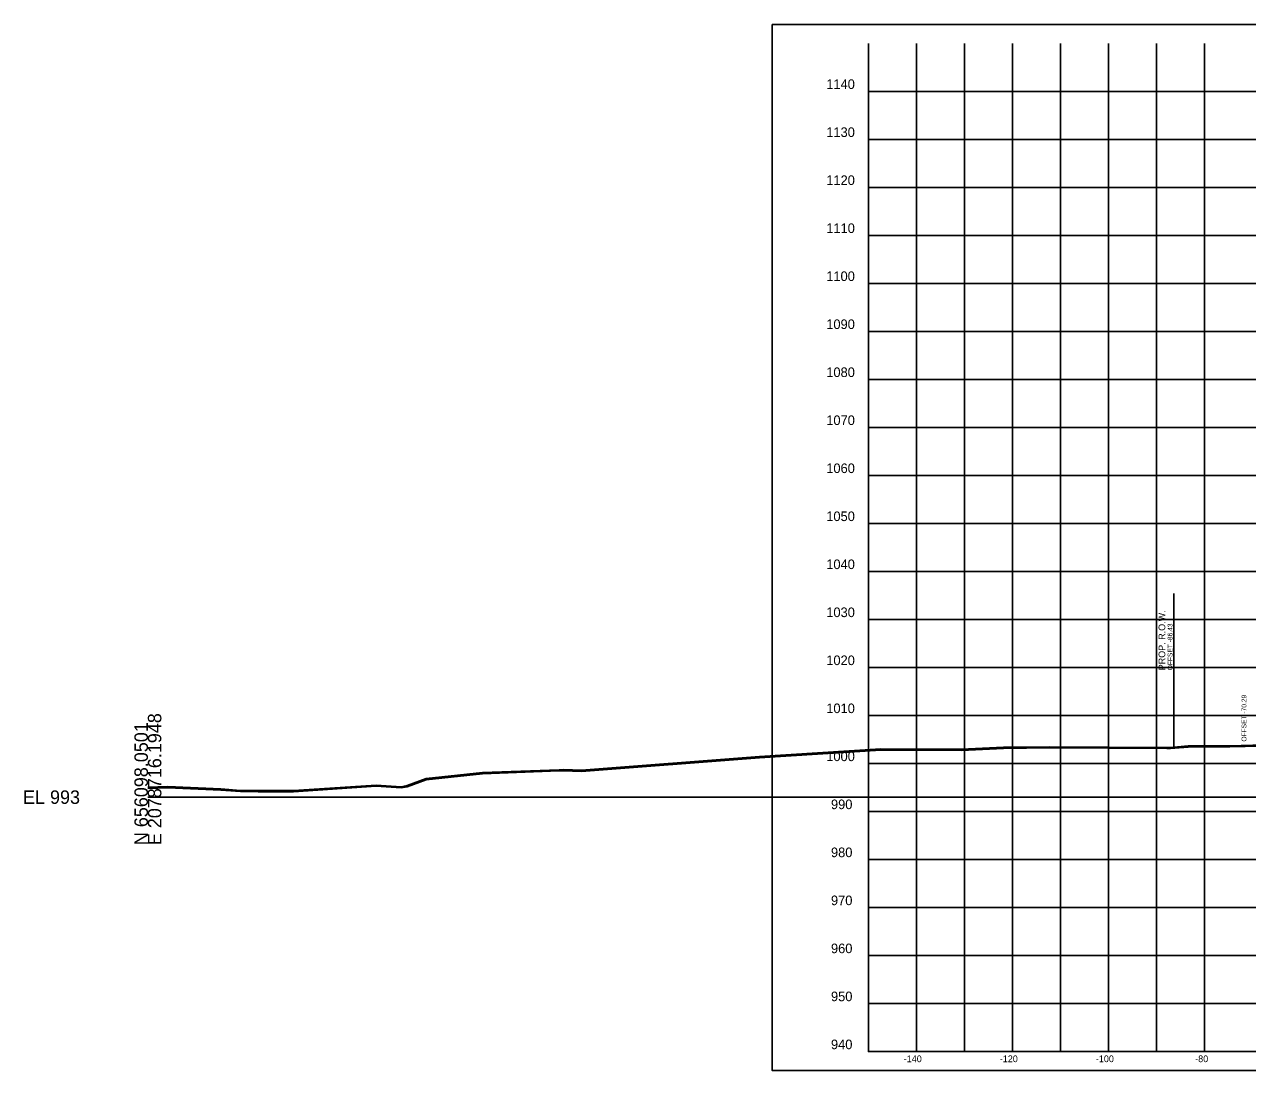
# Model space of a CAD drawing. Extents: x 1131015 to 1136271, y 133453 to 174329.
# Drawn here: x 1131014.8 to 1131269.4, y 159110.7 to 159328.6 of the extents above; entities that cross this region are included whole.
import ezdxf

# ---------------------------------------------------------------- set-up
doc = ezdxf.new("R2010")
doc.units = 0
for name, color, linetype in [('DESIGN - ROW - Right-of-Way and Easement Labels', 7, 'Continuous'), ('DESIGN - ROW - Right-of-Way Linework', 7, 'Continuous'), ('DESIGN - SHEET - Corner Text', 7, 'Continuous'), ('DESIGN - SHEET - Light Grid', 7, 'Continuous'), ('DESIGN - SHEET - Linework', 7, 'Continuous'), ('DESIGN - SHEET - Plot Shape', 7, 'Continuous'), ('DESIGN - TYPICAL - Slope Tie Text', 7, 'Continuous'), ('SURVEY - GROUND - Bottom of Topsoil Layer', 7, 'Continuous'), ('SURVEY - GROUND - Top of Ground', 7, 'Continuous')]:
    doc.layers.add(name, color=color, linetype=linetype)

msp = doc.modelspace()

# ---------------------------------------------------------------- linework, layer by layer
at = {"layer": 'DESIGN - ROW - Right-of-Way Linework'}
msp.add_line((1131254.03, 159178.08), (1131254.03, 159210.08), dxfattribs=at)
at = {"layer": 'DESIGN - SHEET - Light Grid'}
msp.add_line((1131040.46, 159167.66), (1131340.46, 159167.66), dxfattribs=at)
at = {"layer": 'DESIGN - SHEET - Linework'}
for p, q in [((1131200.46, 159114.66), (1131200.46, 159324.66)), ((1131210.46, 159114.66), (1131210.46, 159324.66)), ((1131220.46, 159114.66), (1131220.46, 159324.66)), ((1131230.46, 159114.66), (1131230.46, 159324.66)), ((1131240.46, 159114.66), (1131240.46, 159324.66)), ((1131250.46, 159114.66), (1131250.46, 159324.66)), ((1131260.46, 159114.66), (1131260.46, 159324.66)), ((1131190.46, 159314.66), (1131490.46, 159314.66)), ((1131190.46, 159304.66), (1131490.46, 159304.66)), ((1131190.46, 159294.66), (1131490.46, 159294.66)), ((1131190.46, 159284.66), (1131490.46, 159284.66)), ((1131190.46, 159274.66), (1131490.46, 159274.66)), ((1131190.46, 159264.66), (1131490.46, 159264.66)), ((1131190.46, 159254.66), (1131490.46, 159254.66)), ((1131190.46, 159244.66), (1131490.46, 159244.66)), ((1131190.46, 159234.66), (1131490.46, 159234.66)), ((1131190.46, 159224.66), (1131490.46, 159224.66)), ((1131190.46, 159214.66), (1131490.46, 159214.66)), ((1131190.46, 159204.66), (1131490.46, 159204.66)), ((1131190.46, 159194.66), (1131490.46, 159194.66)), ((1131190.46, 159184.66), (1131490.46, 159184.66)), ((1131190.46, 159174.66), (1131490.46, 159174.66)), ((1131190.46, 159164.66), (1131490.46, 159164.66)), ((1131190.46, 159154.66), (1131490.46, 159154.66)), ((1131190.46, 159144.66), (1131490.46, 159144.66)), ((1131190.46, 159134.66), (1131490.46, 159134.66)), ((1131190.46, 159124.66), (1131490.46, 159124.66))]:
    msp.add_line(p, q, dxfattribs=at)
msp.add_lwpolyline([(1131190.46, 159324.66), (1131190.46, 159114.66), (1131490.46, 159114.66), (1131490.46, 159324.66)], dxfattribs=at)
at = {"layer": 'DESIGN - SHEET - Plot Shape'}
msp.add_lwpolyline([(1131170.46, 159328.6), (1131510.46, 159328.6), (1131510.46, 159110.72), (1131170.46, 159110.72)], close=True, dxfattribs=at)
at = {"layer": 'SURVEY - GROUND - Bottom of Topsoil Layer'}
for p, q in [((1131253.35, 159177.77), (1131257.05, 159178.07)), ((1131257.05, 159178.07), (1131265.71, 159178.13)), ((1131265.71, 159178.13), (1131294.03, 159178.77)), ((1131130.77, 159173.03), (1131167.8, 159175.87)), ((1131167.8, 159175.87), (1131193.04, 159177.44)), ((1131193.04, 159177.44), (1131209.84, 159177.38)), ((1131209.84, 159177.38), (1131218.63, 159177.8)), ((1131218.63, 159177.8), (1131228.19, 159177.92)), ((1131228.19, 159177.92), (1131252.58, 159177.78)), ((1131252.58, 159177.78), (1131253.35, 159177.77)), ((1131110.1, 159172.52), (1131126.11, 159173.11)), ((1131126.11, 159173.11), (1131127, 159173.15)), ((1131127, 159173.15), (1131130.77, 159173.03)), ((1131094.45, 159169.82), (1131098.39, 159171.26)), ((1131098.39, 159171.26), (1131110.1, 159172.52)), ((1131040.46, 159169.49), (1131044.6, 159169.61)), ((1131044.6, 159169.61), (1131055.66, 159169.13)), ((1131055.66, 159169.13), (1131059.73, 159168.81)), ((1131059.73, 159168.81), (1131063.4, 159168.76)), ((1131063.4, 159168.76), (1131070.78, 159168.78)), ((1131070.78, 159168.78), (1131088, 159169.92)), ((1131088, 159169.92), (1131093.2, 159169.59)), ((1131093.2, 159169.59), (1131094.45, 159169.82))]:
    msp.add_line(p, q, dxfattribs=at)
at = {"layer": 'SURVEY - GROUND - Top of Ground'}
for p, q in [((1131209.84, 159177.63), (1131218.63, 159178.05)), ((1131218.63, 159178.05), (1131228.19, 159178.17)), ((1131228.19, 159178.17), (1131252.58, 159178.03)), ((1131252.58, 159178.03), (1131253.35, 159178.02)), ((1131253.35, 159178.02), (1131257.05, 159178.32)), ((1131257.05, 159178.32), (1131265.71, 159178.38)), ((1131265.71, 159178.38), (1131294.03, 159179.02)), ((1131130.77, 159173.28), (1131167.8, 159176.12)), ((1131167.8, 159176.12), (1131193.04, 159177.69)), ((1131193.04, 159177.69), (1131209.84, 159177.63)), ((1131110.1, 159172.77), (1131126.11, 159173.36)), ((1131126.11, 159173.36), (1131127, 159173.4)), ((1131127, 159173.4), (1131130.77, 159173.28)), ((1131094.45, 159170.07), (1131098.39, 159171.51)), ((1131098.39, 159171.51), (1131110.1, 159172.77)), ((1131040.46, 159169.74), (1131044.6, 159169.86)), ((1131044.6, 159169.86), (1131055.66, 159169.38)), ((1131055.66, 159169.38), (1131059.73, 159169.06)), ((1131059.73, 159169.06), (1131063.4, 159169.01)), ((1131063.4, 159169.01), (1131070.78, 159169.03)), ((1131070.78, 159169.03), (1131088, 159170.17)), ((1131088, 159170.17), (1131093.2, 159169.84)), ((1131093.2, 159169.84), (1131094.45, 159170.07))]:
    msp.add_line(p, q, dxfattribs=at)

# ---------------------------------------------------------------- texts
at = {"layer": 'DESIGN - ROW - Right-of-Way and Easement Labels'}
for s, height, p in [('PROP. R.O.W.', 1.4, (1131252.28, 159194.08)), ('OFFSET -86.43', 1, (1131253.78, 159194.08))]:
    msp.add_text(s, height=height, rotation=90, dxfattribs=at).set_placement(p)
at = {"layer": 'DESIGN - SHEET - Corner Text'}
for s, height, p in [('1140', 2, (1131181.7, 159315.16)), ('1130', 2, (1131181.7, 159305.16)), ('1120', 2, (1131181.7, 159295.16)), ('1110', 2, (1131181.7, 159285.16)), ('1100', 2, (1131181.7, 159275.16)), ('1090', 2, (1131181.7, 159265.16)), ('1080', 2, (1131181.7, 159255.16)), ('1070', 2, (1131181.7, 159245.16)), ('1060', 2, (1131181.7, 159235.16)), ('1050', 2, (1131181.7, 159225.16)), ('1040', 2, (1131181.7, 159215.16)), ('1030', 2, (1131181.7, 159205.16)), ('1020', 2, (1131181.7, 159195.16)), ('1010', 2, (1131181.7, 159185.16)), ('1000', 2, (1131181.7, 159175.16)), ('990', 2, (1131182.68, 159165.16)), ('980', 2, (1131182.68, 159155.16)), ('970', 2, (1131182.68, 159145.16)), ('960', 2, (1131182.68, 159135.16)), ('950', 2, (1131182.68, 159125.16)), ('940', 2, (1131182.68, 159115.16)), ('-140', 1.4, (1131197.83, 159112.46)), ('-120', 1.4, (1131217.83, 159112.46)), ('-100', 1.4, (1131237.83, 159112.46)), ('-80', 1.4, (1131258.51, 159112.46))]:
    msp.add_text(s, height=height, dxfattribs=at).set_placement(p)
at = {"layer": 'DESIGN - SHEET - Light Grid'}
for s, p in [('E 2078716.1948', (1131043.26, 159157.66)), ('N 656098.0501', (1131040.46, 159157.66))]:
    msp.add_text(s, height=2.8, rotation=90, dxfattribs=at).set_placement(p)
msp.add_text('EL 993', height=2.8, dxfattribs=at).set_placement((1131014.46, 159166.26))
at = {"layer": 'DESIGN - TYPICAL - Slope Tie Text'}
msp.add_text('OFFSET -70.29', height=1, rotation=90, dxfattribs=at).set_placement((1131269.17, 159179.23))

doc.saveas('drawing.dxf')
